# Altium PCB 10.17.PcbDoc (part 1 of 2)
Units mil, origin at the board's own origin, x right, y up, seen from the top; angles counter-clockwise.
Board outline 3750 x 1920 mil, 2 copper layers (Top Layer, Bottom Layer), stack 30.359 mil thick; 119 components, 118 nets, 550 pads, 365 vias.
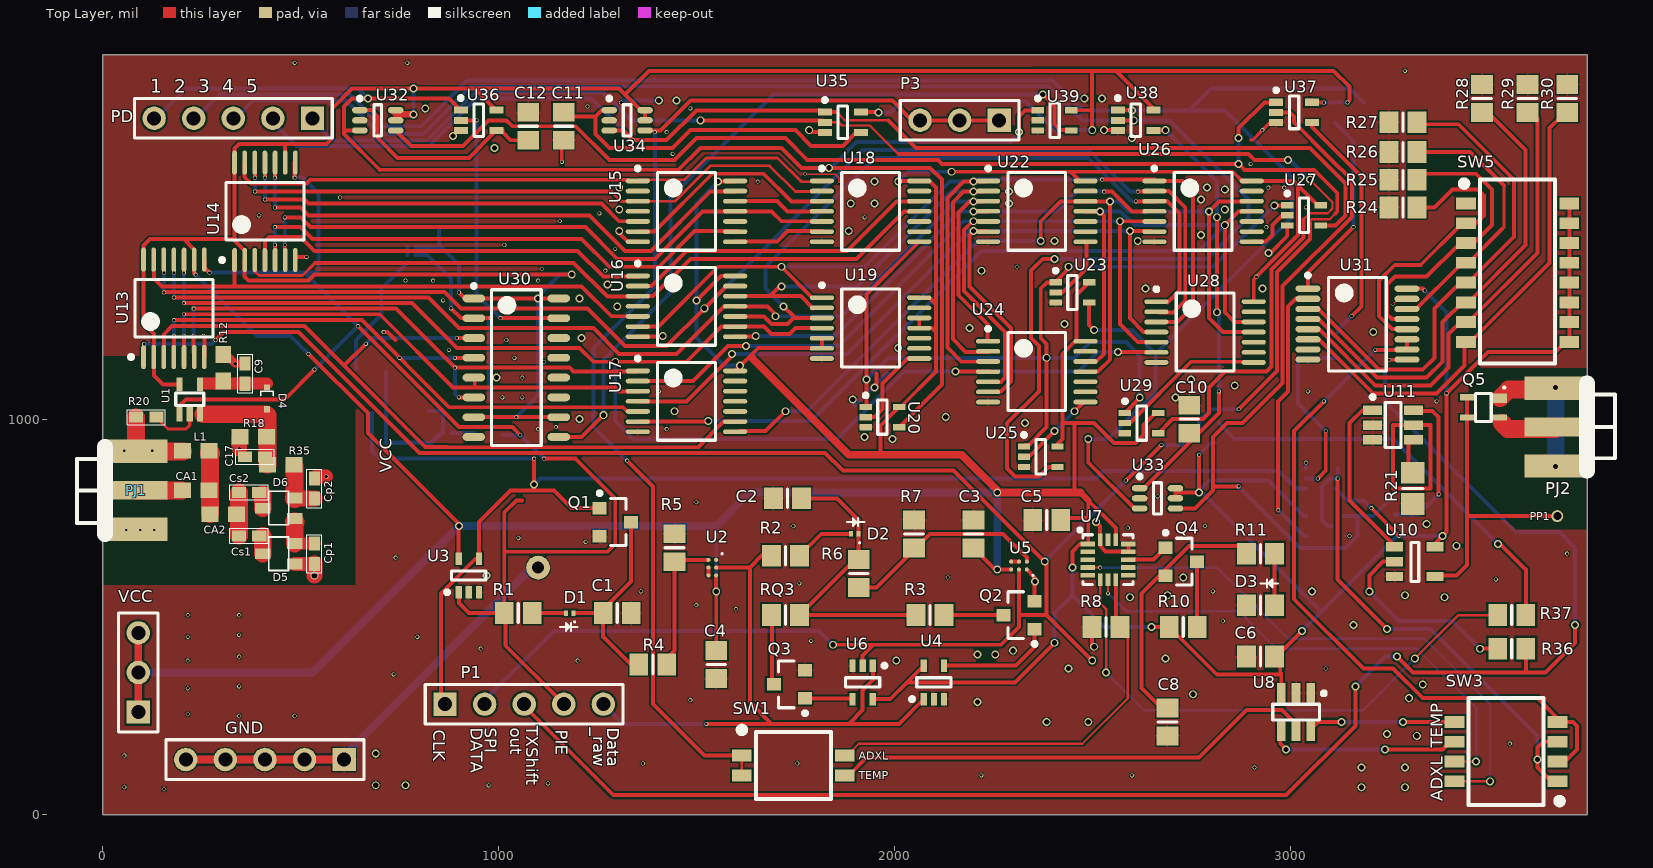
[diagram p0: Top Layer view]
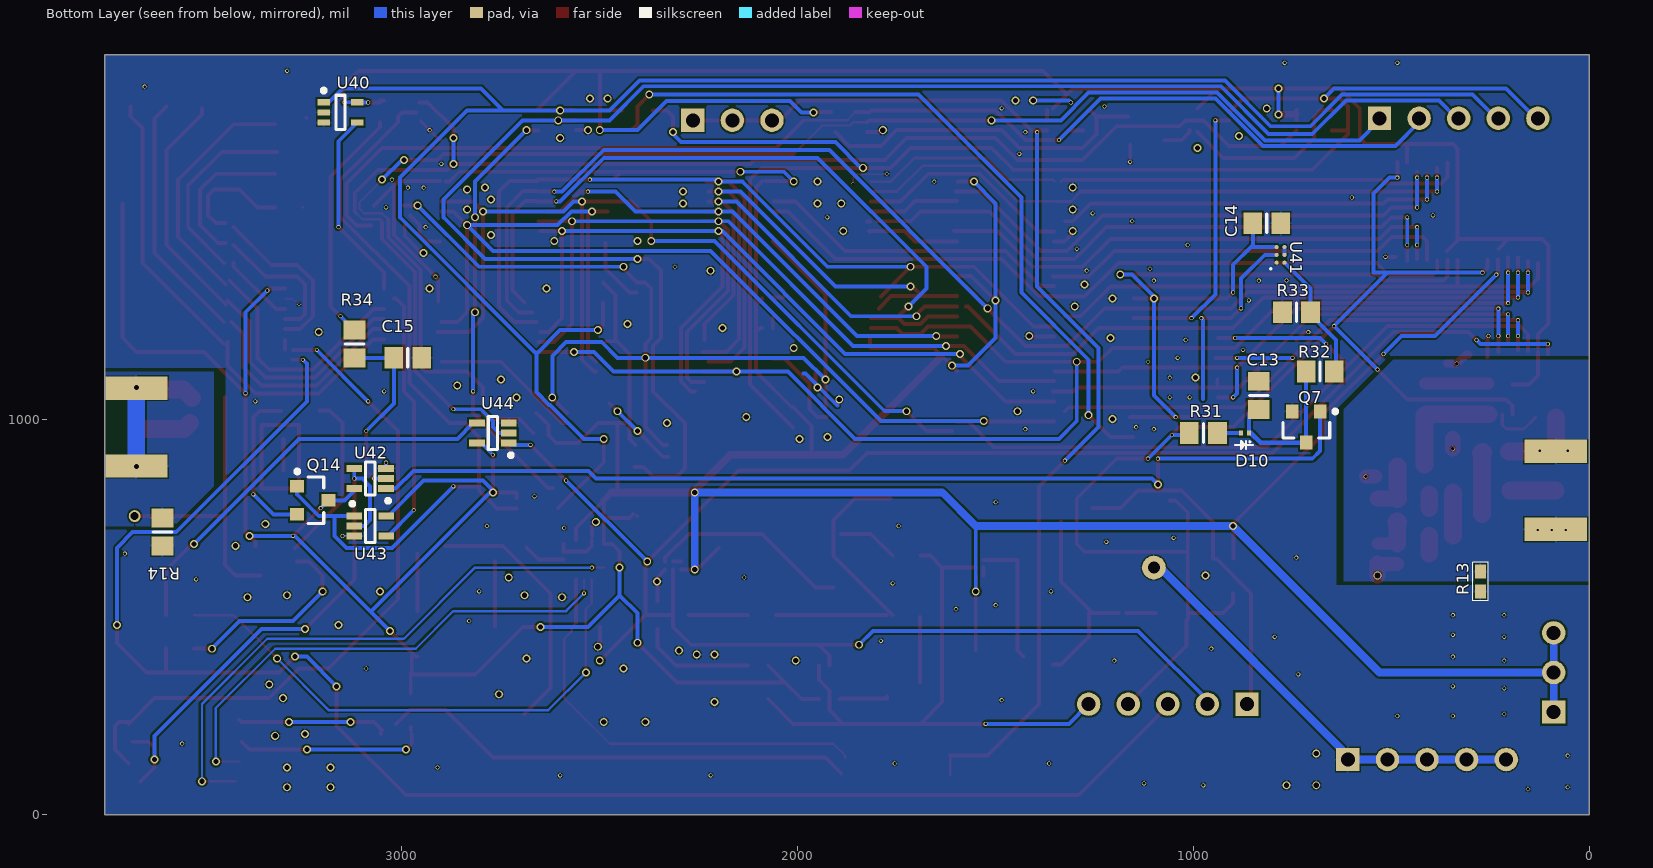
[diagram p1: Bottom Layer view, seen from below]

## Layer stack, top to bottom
Top Solder: solder mask 0.4, Solder Resist, Dk 3.5
Top Layer: signal copper 1.4
Dielectric 1: core 27.5591, FR-4, Dk 4.2
Bottom Layer: signal copper 1.4
Bottom Solder: solder mask 0.4, Solder Resist, Dk 3.5

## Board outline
0,0 3750,0 3750,1920 0,1920

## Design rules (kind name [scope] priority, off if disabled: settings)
Clearance Clearance_1 [InPolygon] p1: gap=5 ignorepadtopadclearanceinfootprint=FALSE except(0: Arc-Hole Track-Hole SMDPad-Hole THPad-Hole Via-Hole Fill-Hole Poly-Hole Region-Hole Text-Hole)
Clearance [All] p2: gap=4 ignorepadtopadclearanceinfootprint=FALSE except(0: Arc-Hole Track-Hole SMDPad-Hole THPad-Hole Via-Hole Fill-Hole Poly-Hole Region-Hole Text-Hole)
ComponentClearance [All] p1 off: gap=4 collisioncheckmode=3 verticalgap=10 showdistances=FALSE
PlaneClearance [All] p1: clearance=0
PolygonConnect [All] p1: connectstyle=Relief reliefconductorwidth=5 reliefentries=4 polygonreliefangle="90 Angle" airgapwidth=3
RoutingVias [All] p1: holewidth=8 width=150 viastyle="Through Hole" minholewidth=28 minwidth=50 maxholewidth=28 maxwidth=50
SolderMaskExpansion [All] p1: expansion=1
Width [All] p1: maxlimit=100 minlimit=4 preferedwidth=8 minimp=50.000000 maximp=50.000000 favimp=50.000000
28 further rules are at their usual default settings.

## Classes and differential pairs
component class Uplink: C5 C6 C8 D3 PJ2 PP1 Q4 Q5 Q14 R8 R10 R11 R14 R21 R24 R25 R26 R27 R28 R29 R30 R36 R37 SW3 SW5 U7 U8 U10 U11 U31
component class PIE_to_SPI: C1 C2 C3 C4 C13 C14 D1 D2 D10 GND P1 Q1 Q2 Q3 Q7 R1 R2 R3 R4 R5 R6 R7 R31 R32 R33 RQ3 U2 U3 U4 U5 U6 U41 VCC
component class AFE: C9 C17 CA1 CA2 Cp1 Cp2 Cs1 Cs2 D4 D5 D6 L1 PJ1 R12 R13 R18 R20 R35 U1
component class FSM: C10 C11 C12 C15 P3 PD R34 SW1 U13 U14 U15 U16 U17 U18 U19 U20 U22 U23 U24 U25 U26 U27 U28 U29 U30 U32 U33 U34 U35 U36 U37 U38 U39 U40 U42 U43 U44

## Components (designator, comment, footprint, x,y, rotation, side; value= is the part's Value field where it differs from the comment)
C1 "4.7nf" 6-0805_N 1300,510 r180 top value=100pF
C2 "4.7nf" 6-0805_N 1730,800 r0 top value=100pF
C3 "100nF" 6-0805_N 2200,710 r270 top value=100pF
C4 "100nF" 6-0805_N 1550,380 r90 top value=100pF
C5 "100nF" 6-0805_N 2385,745 r0 top value=100pF
C6 "100nF" 6-0805_N 2925,400 r0 top value=100pF
C8 "22uF" 6-0805_N 2690,235 r90 top value=100pF
C9 "Ceramic_Chip_Capacitor" 0402 360,1115 r90 top value=1uF
C10 "30pf" 6-0805_N 2745,1000 r270 top value=100pF
C11 "30pf" 6-0805_N 1165,1740 r90 top value=100pF
C12 "30pf" 6-0805_N 1075,1740 r270 top value=100pF
C13 "4.7nf" 6-0805_N 835,1060 r270 bottom value=100pF
C14 "100nF" 6-0805_N 815,1495 r0 bottom value=100pF
C15 "22pf" 6-0805_N 2985,1155 r0 bottom value=100pF
C17 "Ceramic_Chip_Capacitor" 0402 385,905 r180 top value=33pF
CA1 "Ceramic Chip Capacitor" 0603 235,820 r0 top value=tune
CA2 "Ceramic Chip Capacitor" 0603 305,760 r0 top value=tune
Cp1 "Ceramic_Chip_Capacitor" 0402 535,660 r270 top value=10pF
Cp2 "Ceramic_Chip_Capacitor" 0402 535,825 r90 top value=10pF
Cs1 "Ceramic_Chip_Capacitor" 0402 370,705 r0 top value=7pF
Cs2 "Ceramic_Chip_Capacitor" 0402 370,815 r0 top value=7pF
D1 "PMEG1201AESF" DIODE 1180,510 r180 top
D2 "PMEG1201AESF" DIODE 1900,710 r180 top
D3 "LED" 6-0805_N 2925,530 r180 top
D4 "RB751S40T1" SOD-523 415,1080 r0 top
D5 "HSMS-285C" "SOT-323, HSMS-285C" 445,660 r90 top
D6 "HSMS-285C" "SOT-323, HSMS-285C" 445,775 r90 top
D10 "PMEG1201AESF" DIODE 870,965 r0 bottom
GND "Header 5" HDR1X5 610,140 r180 top (schematic designator Pgnd)
L1 "Inductor" 0603 235,920 r0 top value=tune
P1 "Header 5" HDR1X5 865,280 r0 top
P3 "Header 3" HDR1X3 2265,1755 r180 top
PD "Header 5" HDR1X5 530,1760 r180 top (schematic designator P_PD)
PJ1 "SMA" SMA 85.91,819.92 r0 top
PJ2 "SMA" SMA 3670,980 r180 top
PP1 "Probe Point" "Probe Point" 3320,705 r90 top
Q1 "DMG2302UK" NMOS-DMG2302UK 1295,740 r0 top
Q2 "DMG2302UK" NMOS-DMG2302UK 2315,505 r180 top
Q3 "DMG2302UK" NMOS-DMG2302UK 1735,330 r180 top
Q4 "DMG2302UK" NMOS-DMG2302UK 2725,640 r0 top
Q5 "BF1212WR" sot343r 3490,1030 r90 top
Q7 "DMG2302UK" NMOS-DMG2302UK 715,980 r270 bottom
Q14 "DMG2302UK" NMOS-DMG2302UK 3225,795 r180 bottom
R1 "7.5K" 6-0805_N 1050,510 r0 top value=1K
R2 "1.62k" 6-0805_N 1725,655 r0 top value=1K
R3 "9.76K" 6-0805_N 2090,505 r0 top value=1K
R4 "180K" 6-0805_N 1390,380 r0 top value=1K
R5 "410k" 6-0805_N 1445,675 r90 top value=1K
R6 "180K" 6-0805_N 1910,610 r270 top value=1K
R7 "410k" 6-0805_N 2050,710 r90 top value=1K
R8 "1M" 6-0805_N 2535,475 r0 top value=1K
R10 "0R" 6-0805_N 2730,475 r0 top value=1K
R11 "470R" 6-0805_N 2925,660 r180 top value=1K
R12 "Resistor" 0603 305,1130 r270 top value=360k
R13 "Resistor" 0402 275,590 r90 bottom value=0R
R14 "0R" 6-0805_N 3605,715 r270 bottom value=1K
R18 "Resistor" 0603 380,955 r180 top value=412k
R20 "Resistor" 0402 110,1005 r180 top value=0R
R21 "Resistor" 6-0805_M 3310,825 r90 top
R24 "8.4M" 6-0805_N 3285,1535 r180 top value=1K
R25 "8.4M" 6-0805_N 3285,1605 r180 top value=1K
R26 "8.4M" 6-0805_N 3285,1675 r180 top value=1K
R27 "8.4M" 6-0805_N 3285,1750 r0 top value=1K
R28 "8.4M" 6-0805_N 3485,1810 r270 top value=1K
R29 "8.4M" 6-0805_N 3600,1810 r270 top value=1K
R30 "8.4M" 6-0805_N 3700,1810 r270 top value=1K
R31 "100R" 6-0805_N 975,965 r180 bottom value=1K
R32 "180K" 6-0805_N 680,1120 r180 bottom value=1K
R33 "410k" 6-0805_N 740,1270 r0 bottom value=1K
R34 "7.5K" 6-0805_N 3120,1190 r270 bottom value=1K
R35 "Resistor" 0603 450,885 r180 top value=0R
R36 "0R" 6-0805_N 3560,420 r0 top value=1K
R37 "0R" 6-0805_N 3560,505 r180 top value=1K
RQ3 "0R" 6-0805_N 1725,505 r0 top value=1K
SW1 "DIP 1.27*2" KEY1.27*2new 1875,150 r270 top
SW3 "DIP 1.27*4" KEY1.27*4 3675.63,85 r90 top
SW5 "DIP 1.27*8" KEY1.27*8 3444.37,1545 r270 top
U1 "NCS2200SQ2T2G" sc70-5 220,1050 r0 top
U2 "MAX9039B" BGA6-UCSP6 1540.16,625 r270 top
U3 "NL17SZ02DFT2G" "SC-88A (SC-70-5/SOT-353)" 925,605 r90 top
U4 "NL17SZ02DFT2G" "SC-88A (SC-70-5/SOT-353)" 2100,335 r90 top
U5 "MAX9039B" BGA6-UCSP6 2315,630 r180 top
U6 "NL17SZ02DFT2G" "SC-88A (SC-70-5/SOT-353)" 1920,335 r270 top
U7 "ADXL362" ADXL362 2540,645 r0 top
U8 "max6629" MAX6629-6632 3015,260 r270 top
U10 "SN74LV1T86DBVR" "SOT-23-5 -D" 3315,640 r270 top
U11 "LTC6906" LTC6906 3260,985 r0 top
U13 "SN74HC164PW" Tssop14(shift8) 180,1280 r90 top
U14 "SN74HC164PW" Tssop14(shift8) 410,1525 r90 top
U15 "SN74LVC14APW" Tssop14(shift8) 1475,1525 r0 top
U16 "SN74LVC14APW" Tssop14(shift8) 1475,1285 r0 top
U17 "SN74LVC14APW" Tssop14(shift8) 1475,1045 r0 top
U18 "CD74HC30PW" Tssop14(shift8) 1940,1525 r0 top
U19 "CD74HC30PW" Tssop14(shift8) 1940,1230 r0 top
U20 "NL17SZ02DFT2G" "SC-88A (SC-70-5/SOT-353)" 1970,1005 r0 top
U22 "CD74HC30PW" Tssop14(shift8) 2360,1525 r0 top
U23 "NL17SZ02DFT2G" "SC-88A (SC-70-5/SOT-353)" 2450,1320 r0 top
U24 "CD74HC30PW" Tssop14(shift8) 2360,1120 r0 top
U25 "NL17SZ02DFT2G" "SC-88A (SC-70-5/SOT-353)" 2370,905 r0 top
U26 "CD74HC30PW" Tssop14(shift8) 2780,1525 r0 top
U27 "NL17SZ02DFT2G" "SC-88A (SC-70-5/SOT-353)" 3035,1515 r0 top
U28 "CD74HC30PW" Tssop14(shift8) 2785,1220 r0 top
U29 "NL17SZ02DFT2G" "SC-88A (SC-70-5/SOT-353)" 2625,990 r0 top
U30 "SN74LV163ADR(Counter)" SOIC127P600X265-16N 1045,1130 r0 top
U31 "SN74HC165PW" TSSOP16(COUNTER) 3170,1240 r0 top
U32 "NC7SZ175P6X" SC-70 695,1755 r0 top
U33 "NC7SZ175P6X" SC-70 2665,800 r0 top
U34 "NC7SZ175P6X" SC-70 1325,1755 r0 top
U35 "SN74AUP1G32DCK(OR GATE)" SN74AUP1G32DCK（OR-gate-SC70-DCK） 1870,1750 r0 top
U36 "SN74AUP1G32DCK(OR GATE)" SN74AUP1G32DCK（OR-gate-SC70-DCK） 950,1755 r0 top
U37 "SN74AUP1G32DCK(OR GATE)" SN74AUP1G32DCK（OR-gate-SC70-DCK） 3010,1775 r0 top
U38 "SN74AUP1G32DCK(OR GATE)" SN74AUP1G32DCK（OR-gate-SC70-DCK） 2610,1755 r0 top
U39 "NL17SZ02DFT2G" "SC-88A (SC-70-5/SOT-353)" 2405,1755 r0 top
U40 "NL17SZ02DFT2G" "SC-88A (SC-70-5/SOT-353)" 3155,1775 r180 bottom
U41 "MAX9039B" BGA6-UCSP6 780,1415 r90 bottom
U42 "SN74AHC1G08DCK(And gate)" AND-gate-SC70-DCK 3080,850 r0 bottom
U43 "SN74AHC1G08DCK(And gate)" AND-gate-SC70-DCK 3080,730 r180 bottom
U44 "SN74AHC1G08DCK(And gate)" AND-gate-SC70-DCK 2770,965 r0 bottom
VCC "Header 3" HDR1X3 90,260 r90 top (schematic designator Pvcc)

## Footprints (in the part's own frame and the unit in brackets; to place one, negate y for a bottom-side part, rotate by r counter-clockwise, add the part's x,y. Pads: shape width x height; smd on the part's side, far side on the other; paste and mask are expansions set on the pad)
6-0805_M [mm] "Chip Resistor, Body 2.0x1.2mm, IPC Low Density"
  rect 1.4x1.5 smd: 1(-1,0) 2(1,0)
  silkscreen extent 0,-0.65 0,0.65, body extent -1.07,-0.7 1.07,0.7, height 0.7
6-0805_N [mm] "Chip Resistor, Body 2.0x1.2mm, IPC Medium Density"
  rect 1.2x1.4 smd: 1(-0.9,0) 2(0.9,0)
  silkscreen extent 0,-0.6 0,0.6, body extent -1.07,-0.7 1.07,0.7, height 0.7
0402 [mm] "Chip Capacitor; Body 1.0 x 0.5 mm (LxW typ)"
  rect 0.9x0.7 smd: 1(-0.65,0) 2(0.65,0)
  silkscreen extent -1.23,-0.48 1.23,0.48
0603 [mm] "Chip Capacitor; Body 1.6 x 0.8 mm (LxW typ)"
  rect 1.1x1 smd: 1(-0.85,0) 2(0.85,0)
ADXL362 [mm]
  rect 0.925x0.3 smd mask+0.051: 1(-1.3,1) 2(-1.3,0.5) 3(-1.3,0) 4(-1.3,-0.5) 5(-1.3,-1) 9(1.3,-1) 10(1.3,-0.5) 11(1.3,0) 12(1.3,0.5) 13(1.3,1)
  rect 0.3x0.8 smd mask+0.051: 6(-0.5,-1.275) 7(0,-1.275) 8(0.5,-1.275) 14(0.5,1.275) 15(0,1.275) 16(-0.5,1.275)
  silkscreen extent -1.9,-1.6 1.6,2, body extent -1.5,-1.5 1.5,1.5, height 1.14
AND-gate-SC70-DCK [mm] "SOT23, 5-Leads, Body 2.10x2.35mm, Pitch 0.65mm, IPC Medium Density"
  rect 1x0.45 smd: 1(-1.016,0.65) 2(-1.016,0) 3(-1.016,-0.65) 4(1.023,-0.65) 5(1.023,0.65)
  silkscreen extent -1.27,-1.05 0.3,1.55, body extent -0.7,-1.05 0.7,1.05, height 1.1
BGA6-UCSP6 [mm] "BGA, 6-Leads, Body 1.57x1.05mmx0.69mm, Pitch 1.00mm"
  round 0.26 smd: A1(-0.5,0.25) A2(0,0.25) A3(0.5,0.25) B1(-0.5,-0.25) B2(0,-0.25) B3(0.5,-0.25)
  silkscreen extent -0.94,0.58 -0.84,0.68, body extent -0.78,-0.53 0.79,0.53, height 0.69
DIODE [mm] "DFN, 2-Leads, Body 0.30x0.60mm, Pitch 0.40mm, IPC Medium Density"
  rect 0.25x0.35 smd: 1(-0.25,0) 2(0.25,0)
  silkscreen extent -0.37,0.52 -0.27,0.61, body extent -0.32,-0.17 0.31,0.16, height 0.32
HDR1X3 [mm] "Connector; Header; 3 Position"
  rect 1.5x1.5 hole 0.9: 1(0,0)
  round 1.5 hole 0.9: 2(2.54,0) 3(5.08,0)
  silkscreen extent -1.27,-1.27 6.35,1.27
HDR1X5 [mm] "Connector; Header; 5 Position"
  rect 1.5x1.5 hole 0.9: 1(0,0)
  round 1.5 hole 0.9: 2(2.54,0) 3(5.08,0) 4(7.62,0) 5(10.16,0)
  silkscreen extent -1.27,-1.27 11.43,1.27
KEY1.27*2new [mm]
  rect 0.76x1.27 smd: 1(0,-6.62) 2(1.27,-6.62) 3(0,0) 4(1.27,0)
  silkscreen extent -1.83,-6.78 2.79,-0.89
KEY1.27*4 [mm]
  rect 0.76x1.27 smd: 1(0,0) 2(1.27,0) 3(2.54,0) 4(3.81,0) 5(3.81,6.62) 6(2.54,6.62) 7(1.27,6.62) 8(0,6.62)
  silkscreen extent -1.52,-0.31 5.33,5.71
KEY1.27*8 [mm]
  rect 0.76x1.27 smd: 1(0,0) 2(1.27,0) 3(2.54,0) 4(3.81,0) 5(5.08,0) 6(6.35,0) 7(7.62,0) 8(8.89,0) 9(8.89,6.62) 10(7.62,6.62) 11(6.35,6.62) 12(5.08,6.62) 13(3.81,6.62) 14(2.54,6.62) 15(1.27,6.62) 16(0,6.62)
  silkscreen extent -1.52,-0.31 10.29,5.72
LTC6906 [mm] "SOT23, 6-Leads, Body 2.90x2.80mm, Pitch 0.95mm, IPC Medium Density"
  rect 1.22x0.6 smd: 1(-1.31,0.95) 2(-1.31,0) 3(-1.31,-0.95) 4(1.31,-0.95) 5(1.31,0) 6(1.31,0.95)
  silkscreen extent -1.43,-1.45 0.5,1.92, body extent -0.87,-1.45 0.87,1.45, height 1
MAX6629-6632 [mm] "SOT23, 6-Leads, Body 2.90x2.80mm, Pitch 0.95mm, IPC Medium Density"
  rect 1.33x0.56 smd: 1(-1.2,0.95) 2(-1.2,0) 3(-1.2,-0.95) 4(1.2,-0.95) 5(1.2,0) 6(1.2,0.95)
  silkscreen extent -1.32,-1.5 0.5,1.91, body extent -0.87,-1.5 0.87,1.5, height 1.45
NMOS-DMG2302UK [mm]
  rect 0.9x0.8 smd: 1(-1,0.9) 2(-1,-0.9) 3(1,0)
  silkscreen extent -1.12,-1.5 0.7,1.97, body extent -0.7,-1.5 0.7,1.5, height 1.1
"Probe Point" [mil] "35mil Pad, 20mil hole size"
  round 30 hole 20: 0(50,-355)
sc70-5 [mm] "SC70-5"
  rect 0.4x0.92 smd: 1(-0.65,-0.95) 2(0,-0.95) 3(0.65,-0.95) 4(0.65,0.95) 5(-0.65,0.95)
  silkscreen extent -0.9,-0.4 0.9,0.4
SC-70 [mm] "SOP, 6-Leads, Body 2.00x1.25mm, Pitch 0.65mm, IPC Medium Density"
  oval 1x0.4 smd: 1(-1.15,0.65) 2(-1.15,0) 3(-1.15,-0.65) 4(1.15,-0.65) 5(1.15,0) 6(1.15,0.65)
  silkscreen extent -1.27,-1 0.25,1.52, body extent -0.65,-1 0.65,1, height 2.65
"SC-88A (SC-70-5/SOT-353)" [mm] "SOT23, 5-Leads, Body 2.00x2.10mm, Pitch 0.65mm, IPC Medium Density"
  rect 0.8x0.4 smd: 1(-1.075,0.65) 2(-1.075,0) 3(-1.075,-0.65) 4(1.075,-0.65) 5(1.075,0.65)
  silkscreen extent -1.2,-1.1 0.3,1.52, body extent -0.67,-1.1 0.67,1.1, height 1.1
SMA [mm]
  rect 4x1.2 smd: 1(-0.023,0.002)
  rect 4x1.5 smd: 2(-0.023,-2.498) 2(-0.023,2.502)
  rect 4x1.5 smd far side: 2(-0.023,-2.498) 2(-0.023,2.502)
  silkscreen extent -3.83,-2.8 -1.93,2.8
SN74AUP1G32DCK（OR-gate-SC70-DCK） [mm] "SOT23, 5-Leads, Body 2.10x2.35mm, Pitch 0.65mm, IPC Medium Density"
  rect 0.9x0.45 smd: 1(-1.15,0.65) 2(-1.15,0) 3(-1.15,-0.65) 4(1.15,-0.65) 5(1.15,0.65)
  silkscreen extent -1.27,-1.05 0.3,1.55, body extent -0.7,-1.05 0.7,1.05, height 1.1
SOD-523 [mm] "SOD-523 Footprint"
  rect 0.4x0.4 smd: 1(0,0) 2(0,-1.4)
  silkscreen extent -0.4,-0.53 0.4,-0.25
SOIC127P600X265-16N [mm] "SOIC, 16-Leads, Body 10.00x4.00mm, Pitch 1.27mm, IPC Medium Density"
  oval 1.45x0.5 smd: 1(-2.725,4.445) 2(-2.725,3.175) 3(-2.725,1.905) 4(-2.725,0.635) 5(-2.725,-0.635) 6(-2.725,-1.905) 7(-2.725,-3.175) 8(-2.725,-4.445) 9(2.725,-4.445) 10(2.725,-3.175) 11(2.725,-1.905) 12(2.725,-0.635) 13(2.725,0.635) 14(2.725,1.905) 15(2.725,3.175) 16(2.725,4.445)
  silkscreen extent -2.85,-5 1.6,5.37, body extent -2,-5 2,5, height 2.65
sot343r [mm] "SOT343R Package for BF1212"
  rect 0.6x0.92 smd: 1(0.584,-1.016)
  rect 0.4x0.92 smd: 2(-0.664,-1.007) 3(-0.664,1.093) 3(0.636,1.093)
  silkscreen extent -0.91,-1.3 1.27,0.54
"SOT-23-5 -D" [mm] "SOT-23/SC-74A; 5 Leads; Body 3 x 3.1 mm, inc. leads (LxW max)"
  rect 0.6x1.1 smd: 1(-0.95,-1.3) 2(0,-1.3) 3(0.95,-1.3) 4(0.95,1.3) 5(-0.95,1.3)
  silkscreen extent -1.22,-0.25 1.27,0.25
"SOT-323, HSMS-285C" [mm] "SOT-323/SC-70; 3 Leads; HSMS-285C"
  rect 0.7x1 smd: 1(-0.65,-1.025) 2(0.65,-1.025) 3(0,1.025)
  silkscreen extent -1.07,-0.65 1.07,0.65
Tssop14(shift8) [mm] "SOP, 14-Leads, Body 5.00x4.50mm, Pitch 0.65mm, IPC Medium Density"
  oval 1.55x0.3 smd: 1(-3.125,1.95) 2(-3.125,1.3) 3(-3.125,0.65) 4(-3.125,0) 5(-3.125,-0.65) 6(-3.125,-1.3) 7(-3.125,-1.95) 8(3.125,-1.95) 9(3.125,-1.3) 10(3.125,-0.65) 11(3.125,0) 12(3.125,0.65) 13(3.125,1.3) 14(3.125,1.95)
  silkscreen extent -3.25,-2.5 1.85,2.87, body extent -2.25,-2.5 2.25,2.5, height 2.65
TSSOP16(COUNTER) [mm] "SOP, 16-Leads, Body 6.00x4.50mm, Pitch 0.65mm, IPC Medium Density"
  oval 1.6x0.4 smd: 1(-3.175,2.275) 2(-3.175,1.625) 3(-3.175,0.975) 4(-3.175,0.325) 5(-3.175,-0.325) 6(-3.175,-0.975) 7(-3.175,-1.625) 8(-3.175,-2.275) 9(3.175,-2.275) 10(3.175,-1.625) 11(3.175,-0.975) 12(3.175,-0.325) 13(3.175,0.325) 14(3.175,0.975) 15(3.175,1.625) 16(3.175,2.275)
  silkscreen extent -3.3,-3 1.85,3.25, body extent -2.25,-3 2.25,3, height 2.65

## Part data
C1 C2 C3 C4 C5 C6 C8 C10 C11 C12 C13 C14 C15: library part Cap, "Capacitor"
C9 C17 CA1 CA2 Cp1 Cp2 Cs1 Cs2: "Ceramic Capacitor - Standard"
D1 D2 D10: library part DIODE, "Schottky Diode"
D3: library part LED0, "Typical INFRARED GaAs LED"
D4: library part "Schottky Diode", "Schottky Diode"
D5 D6: "Agilent Schottky Diode, Bridge Quad, HSMS-285C"
GND P1 PD: "Header, 5-Pin"
P3 VCC: "Header, 3-Pin"
PP1: "Probe Point for debug"
Q1 Q2 Q3 Q4 Q7 Q14: library part MOSFET-N, "N-Channel MOSFET", PackageDocument=1995/1996
Q5: library part BF1212
R1 R2 R3 R4 R5 R6 R7 R8 R10 R11 R14 R24 R25 R26 R27 R28 R29 R30 R31 R32 R33 R34 R36 R37 RQ3: library part Res2, "Resistor"
R12 R13 R18 R20 R21 R35: "Thick Film Resistor"
SW1: library part KEY1.27*2
SW3: library part KEY1.27*4
SW5: library part KEY1.27*8
U1: "On Semi 10uA Comparator"
U2 U5 U41: library part Comparator
U3 U4 U6 U20 U23 U25 U27 U29 U39 U40: library part "NOR GATE"
U7: "Analog Devices low power accelerometer"
U10: library part "XOR GATE"
U13 U14: library part SN74HC164
U30: library part SN74LV163APW(Counter)

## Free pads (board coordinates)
  round 60 hole 30: 0(1100,625)

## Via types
v1: diameter 20, hole 13, Top Layer to Bottom Layer, 179 vias
v2: diameter 10, hole 6.5, Top Layer to Bottom Layer, 137 vias
v3: diameter 10, hole 7, Top Layer to Bottom Layer, 28 vias
v4: diameter 10, hole 8, Top Layer to Bottom Layer, 10 vias
v5: diameter 10, hole 6, Top Layer to Bottom Layer, 7 vias
v6: diameter 8, hole 6, Top Layer to Bottom Layer, 2 vias
v7: diameter 20, hole 15, Top Layer to Bottom Layer, 1 vias
v8: diameter 10, hole 6.5, Top Layer to Bottom Layer, tented top, 1 vias

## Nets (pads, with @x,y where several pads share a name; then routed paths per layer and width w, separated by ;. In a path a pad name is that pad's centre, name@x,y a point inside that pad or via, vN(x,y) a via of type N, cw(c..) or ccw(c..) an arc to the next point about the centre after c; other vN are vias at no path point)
ACCINT: Q4.1 U7.11 | length 106.9
  Top Layer w10: U7.11@2591.18,645 2655,645 ; 2655.2,645 Q4.1@2685.63,675.43
ADXL_CS: R8.2 SW1.3 U7.8 | length 1087.4
  Top Layer w6: SW1.3@1880,145 1880,150 1910,180 2475,180 2590,295 2590,445 2570.43,464.57 R8.2@2570.43,475 R8.2@2559.69,485.75
  Top Layer w10: R8.2@2559.69,485.75 U7.8@2559.69,594.8
ANT: CA1.1 PJ1.1 | length 115
  Top Layer w45: PJ1.1@85,820 CA1.1@200,820
B: R24.1 SW5.2 U31.12 | length 727.2
  Top Layer w10: U31.12@3295,1227.2 3257.8,1227.2 3225,1260 3225,1350 3265,1390 3330,1390 SW5.2@3425,1485 ; R24.1@3320.43,1535 3365,1535 3410,1580 3475,1580 3490,1565 3490,1515 3470,1495 SW5.2@3445,1495
"Bit avrg": C9.1 D4.1 R12.2 U1.4 | length 167.4
  Top Layer w8: U1.4@245,1090 U1.4@245.12,1090.12 ; C9.1@360,1085 C9.1@365.12,1090.12
  Top Layer w30: 255,1090.12 365.12,1090.12 415,1090.12
BITLINE: C17.1 D4.2 R18.1 R35.2 U1.3 | length 288.2
  Top Layer w12: 412.4,1012.6 415,1010 ; 415,930 416.54,928.46
  Top Layer w45: 255,1012.6 412.4,1012.6 ; R35.2@416.54,885 416.54,928.46 416.54,1010
C: R25.1 SW5.3 U31.13 | length 731.7
  Top Layer w10: U31.13@3295,1252.8 3257.2,1252.8 3245,1265 3245,1340 3265,1360 3345,1360 SW5.3@3425,1440 ; R25.1@3320,1620 3470,1620 3510,1580 3510,1490 3465,1445 SW5.3@3445,1445
CLK: P1.1 Q1.1 Q7.1 U3.4 U42.1 | length 3433.9
  Top Layer w10: P1.1@860,285 855,290 855,560 942.32,647.32 U3.4@950.59,647.32 950.59,740.59 1030,820 1090,820 ; v2(1090,900) v1(1090,835) 1090,820 ; Q1.1@1255,775 1185,775 1140,820 1090,820
  Bottom Layer w10: Q7.1@680,1015 680,920 700,900 v2(1090,900) ; v1(1090,835) 1105,850 2510,850 2529,869 2971,869 3015.59,824.41 U42.1@3040,824.41
CLK_ADXL: SW3.8 U7.4 | length 1442.5
  Top Layer w6: U7.4@2488.82,625.32 2520.32,625.32 v5(2520,625) ; SW3.8@3419.37,85 3500,85 v1@3505,80
  Bottom Layer w6: v5(2520,625) 2815,625 2995,445 3340,445 3505,280 v1(3505,85)
CLK_TEMP: SW3.6 U8.4 | length 479.1
  Top Layer w10: U8.4@2975,205 2975,180 v1(2990,165) ; U8.4@2977.6,212.76 U8.4@2977.6,222.4 ; v1(3240,165) 3385,165 SW3.6@3405,185
  Bottom Layer w10: v1(2990,165) v1(3240,165)
"CONTROL BIT": P3.1 P3.2 P3.3 SW1.1 SW1.2 U34.4 | length 2845.2
  Top Layer w6: SW1.1@1612.5,147.5 1614.37,145.63 SW1.2@1614.37,100
  Top Layer w10: v2(1325,895) 1390,830 1390,280 1520,150 SW1.1@1614.37,150 SW1.1@1615,150 ; U34.4@1370.28,1729.41 1409.41,1729.41 1485,1805 1995,1805 2045,1755 2140,1755 2240,1755 P3.1@2265,1755
  Bottom Layer w10: v2(1325,895) 1240,980 1240,1180 1395,1335 v2(1395,1725)
D: R26.1 SW5.4 U31.14 | length 679
  Top Layer w8: 3535,1480 3540,1485 3540,1590
  Top Layer w10: U31.14@3295,1278.39 3318.39,1278.39 3425,1385 SW5.4@3425,1395 ; R26.1@3315,1675 3455,1675 3540,1590 ; SW5.4@3447.69,1395 3450,1395 3535,1480
DATA-CONTROL: U32.4 U37.1 U44.2 | length 3579.2
  Top Layer w6: 3050,1495 3050,1500 3055,1505 3100,1505 3115,1520
  Top Layer w10: U32.4@740.28,1729.41 779.69,1690 910,1690 975,1755 1020,1755 1035,1740 1195,1740 1280,1655 1445,1655 1460,1670 1500,1710 1725,1710 1780,1655 2110,1655 2120,1645 v1(2870,1645) 2885,1630 3060,1630 3119,1571 3119,1524 3115,1520 ; v1(2870,1710) 2870,1735 2935,1800 U37.1@2955,1800 ; v2@2870.43,1025.43 2967,1122 2967,1372 3050,1455 3050,1495
  Bottom Layer w10: U44.2@2740,965 2755,965 2770,980 2770,995 2800,1025 v2(2870,1025) ; v1(2870,1645) v1@2870,1705
DATA_RAW: P1.5 R2.1 U2.A2 U4.1 U6.1 | length 1615.3
  Top Layer w10: P1.5@1255,280 1260,285 P1.5@1255,285 ; v2(1525,230) 1690,230 ; U2.A2@1550,625 1635,625 ; R2.1@1689.57,655 1665,655 1635,625 ; U6.1@1945.59,377.32 1945.59,340.59 1920,315 1920,265 1885,230 ; U4.1@2074.41,292.68 2011.73,230 1885,230 ; 1635,625 1635,285 1690,230 ; 1690,230 1885,230
  Bottom Layer w10: P1.5@1260,280 P1.5@1265,280 1315,230 v2(1525,230)
DATAIN_ADXL: R37.2 U7.6 | length 1369.6
  Top Layer w6: U7.6@2520.31,594.8 2520.31,534.69 2535,520 v1(2535,360) ; v1(3315,395) 3425,505 R37.2@3525,505
  Bottom Layer w6: v1(2535,360) 2630,265 3185,265 v1(3315,395)
DL1-EN: C12.2 U32.1 U36.4 | length 528.3
  Top Layer w8: C12.2@1075,1704.57 C12.2@1075.43,1704.57
  Top Layer w10: U32.1@649.72,1780.59 679.41,1780.59 695,1765 695,1710 745,1660 925,1660 U36.4@990,1725 ; U36.4@1010,1730 1010,1725 1030.43,1704.57 C12.2@1075,1704.57
DL2-EN: C10.2 U33.1 U38.4 | length 1078.8
  Top Layer w10: U33.1@2619.72,825.59 2630.59,825.59 2820,1015 v2(2820,1070) ; U38.4@2655.28,1729.41 v1@2684.41,1729.41 ; v1(2815,1270) v1(2815,1510)
  Bottom Layer w10: v1(2685,1730) 2815,1600 v1(2815,1510) ; v1(2815,1270) 2820,1265 v2(2820,1070)
DL3-EN: C11.2 U34.1 U35.4 | length 875.4
  Top Layer w10: C11.2@1165,1765 1245,1765 ; U34.1@1265,1780 1260,1780 1245,1765 ; U35.4@1905,1725 1870,1690 1790,1690 1750,1730 1485,1730 1440,1685 1280,1685 1245,1720 1245,1765
E: R27.2 SW5.5 U31.3 | length 1237.7
  Top Layer w10: U31.3@3045,1278.39 3071.61,1278.39 3225,1125 3335,1125 3365,1155 3365,1280 SW5.5@3435,1350 ; R27.2@3320,1745 3425,1745 3565,1605 3565,1460 SW5.5@3445,1340
F: R28.2 SW5.6 U31.4 | length 1190
  Top Layer w10: U31.4@3045,1252.8 3072.2,1252.8 3220,1105 3345,1105 3385,1145 3385,1245 SW5.6@3440,1300 ; SW5.6@3445,1290 3595,1440 3595,1680 3505,1770 R28.2@3505,1785
G: R29.2 SW5.7 U31.5 | length 1189.9
  Top Layer w10: U31.5@3045,1227.2 3072.8,1227.2 3215,1085 3355,1085 3400,1130 3400,1215 SW5.7@3430,1245 ; SW5.7@3450,1245 3625,1420 3625,1760 R29.2@3595,1790
GND: C1.1 C2.1 C3.1 C4.1 C5.1 C6.1 C8.1 C10.1 C11.1 C12.1 C13.1 C14.1 C15.1 D3.2 GND.1 GND.2 GND.3 GND.4 GND.5 pad.0 Q1.2 Q2.2 Q3.2 Q7.2 R5.2 R7.2 R8.1 R13.1 R14.2 R21.1 R24.2 R25.2 R26.2 R27.1 R28.1 R29.1 R30.1 R33.2 U2.A1 U3.2 U3.3 U4.2 U4.3 U5.A1 U6.3 U7.12 U7.13 U7.16 U8.1 U8.2 U10.3 U11.2 U11.3 U13.7 U14.7 U15.7 U16.7 U17.7 U18.7 U19.7 U20.3 U22.7 U23.3 U24.7 U25.3 U26.7 U27.3 U28.7 U29.3 U30.8 U31.8 U31.15 U32.2 U33.2 U34.2 U35.3 U36.3 U37.3 U38.3 U39.2 U39.3 U40.2 U40.3 U41.A1 U42.3 U43.3 U44.3 | length 2723
  Top Layer w4: v2(1775,1620) 1776,1619 1851,1619 1860,1610 v6(1860,1595) ; v2(2900,1645) v2@2901,1644 ; v6(3260,1290) U31.15@3270,1300 ; U31.15@3273.98,1303.98 U31.15@3295,1303.98
  Top Layer w8: v2(1160,1650) C11.1@1160,1695 ; 2900.12,1705 2905,1705 v2(2930,1730) U37.3@2952.5,1752.5 ; R27.1@3240,1760 R27.1@3242.5,1762.5
  Top Layer w10: U13.7@256.77,1156.97 v3@256.77,1206.77 ; U14.7@490,1410 v3(515,1410) ; v2(710,1220) 720,1220 740,1200 ; v1@1300,1475 v1(1305,1475) ; 1310,1465 1326.77,1448.23 U15.7@1351.97,1448.23 ; U16.7@1351.97,1208.23 1413.23,1208.23 v1(1415,1210) ; v1@1790,1725 U35.3@1825,1725 ; v1(1950,1080) 1955,1085 1955,1115 ; U5.A1@2334.69,620.16 2354.37,600.47 Q2.2@2354.37,540.43 ; R8.1@2499.57,475 2499.57,430.43 v1(2505,425) ; v1(2510,740) 2520,730 U7.16@2520,705 ; U7.16@2520.31,695.2 2520.31,679.69 2534,666 2589.87,666 U7.12@2591.18,664.69 U7.13@2591.18,684.37 ; v1(2530,1730) U38.3@2560,1730 ; v1@2945,1425 v1(2945,1420) 2950,1420 2992.68,1462.68 U27.3@2992.68,1489.41
  Top Layer w20: GND.5@205,135 GND.5@210,140 GND.4@310,140 GND.3@410,140 GND.2@510,140 GND.1@610,140
  Bottom Layer w4: U43.3@3135,705 v4(3150,705)
  Bottom Layer w10: v4(1310,1800) 1315,1805 v1(1405,1805) ; 1900,1035 1980,1115 1985,1115 ; U42.3@3040,875 U42.3@3040,875.59 v2(3040,890)
  Bottom Layer w20: GND.5@210,140 GND.4@310,140 GND.3@410,140 GND.2@510,140 GND.1@600,140 ; GND.1@605,140 GND.1@600,140 ; pad.0@1090,630 GND.1@600,140
  other v1: 3180,70 3290,70 690,75 765,75 3180,120 3290,120 690,155 3320,200 3245,205 2385,235 2490,235 2210,285 3300,295 2755,305 3335,330 2440,370 2005,390 2685,395 2210,405 2255,405 2300,415 3160,480 2595,550 3390,550 2690,555 3290,555 3055,565 2355,590 2730,600 970,605 3420,680 3345,735 1995,950 1925,955 2330,990 1205,1000 2130,1005 1445,1020 1895,1050 2710,1055 2860,1085 2750,1100 995,1105 2010,1180 1210,1205 3210,1220 2190,1230 2430,1240 1300,1285 1205,1305 2635,1330 2930,1330 1275,1340 2220,1375 2405,1450 2615,1450 2775,1465 1885,1475 1305,1530 2835,1530 1890,1545 1950,1545 2290,1545 2775,1555 2290,1575 2835,1580 1305,1585 2790,1585 1950,1600 2600,1710 885,1715 1785,1730 815,1785 1450,1805 2480,1810 2525,1810
  other v2: 155,65 55,70 975,75 1125,80 2220,100 2600,100 2910,120 1365,130 1755,130 55,150 3555,180 345,250 485,250 215,255 1485,290 215,320 345,325 735,355 3090,370 215,390 1200,390 345,400 955,420 1790,440 215,450 795,450 345,455 2830,490 215,505 345,505 1600,520 1500,530 1360,565 2805,565 1760,585 3520,595 2135,600 740,650 3700,660 1220,690 1050,700 2590,725 1745,730 2785,730 1500,790 2665,805 1100,975 1425,975 1145,980 3370,1045 1010,1055 1060,1055 1405,1070 3045,1070 1060,1105 1115,1145 1040,1155 875,1175 1020,1200 860,1300 835,1350 1100,1350 1270,1375 1110,1380 2310,1385 1295,1430 1015,1440 2940,1485 1155,1500 1925,1510 395,1515 1255,1520 3040,1535 600,1560 2945,1585 2985,1585 1655,1600 3025,1605 1440,1670 1425,1725 1485,1785 3650,1840 3290,1880 485,1900 770,1900
  other v3: 255,1210 765,1350
  other v4: 1225,1790
H: R30.2 SW5.8 U31.6 | length 1237.8
  Top Layer w10: U31.6@3045,1201.61 3073.39,1201.61 3210,1065 3370,1065 3440,1135 SW5.8@3440,1195 ; SW5.8@3450,1190 3655,1395 3655,1735 3685.22,1765.22 R30.2@3685.22,1789.78
LOAD: U30.9 U39.4 | length 1932.2
  Top Layer w10: U30.9@1152.28,955 1210,955 v1(1265,1010) ; v1(2375,1820) 2405,1790 2405,1745 2420,1730 U39.4@2440,1730
  Bottom Layer w10: v1(1265,1010) 1265,1150 1435,1320 1435,1560 1695,1820 v1(2375,1820)
NetC1_2: C1.2 D1.1 Q1.3 R4.1 | length 509.4
  Top Layer w10: D1.1@1189.84,510 C1.2@1264.57,510 1264.57,450 ; C1.2@1259.78,514.78 1334.37,589.37 Q1.3@1334.37,740 ; 1265,450 1335,380 R4.1@1354.57,380
NetC2_2: C2.2 D2.1 R3.1 R6.1 RQ3.2 | length 748.5
  Top Layer w10: RQ3.2@1760.43,505 1909.84,654.41 D2.1@1909.84,710 1909.84,745.16 1855,800 C2.2@1765.43,800 ; RQ3.2@1775.28,505 R3.1@2054.57,505
NetC8_2: C8.2 Q4.2 R11.2 | length 646.2
  Top Layer w10: C8.2@2690,255.43 2625,320.43 2625,560 2745,680 R11.2@2890,680
NetC13_2: C13.2 D10.1 Q7.3 R32.1 | length 417
  Bottom Layer w10: Q7.3@715,940 715.43,940.43 715.43,940.63 R32.1@715.43,1120 ; C13.2@825,1020 855,1020 860.16,1014.84 D10.1@860.16,965
  Bottom Layer w12: Q7.3@715.43,940.63 830.63,940.63 855,965
NetC15_2: C15.2 R34.2 U42.2 | length 471.7
  Top Layer w10: v2(3070,850) 3090,870 v2(3090,970)
  Bottom Layer w10: C15.2@3020.43,1155 C15.2@3020.43,1154.57 ; U42.2@3040,850 v2(3070,850) ; v2(3090,970) 3020.43,1039.57 C15.2@3020.43,1154.57 ; R34.2@3120,1154.57 C15.2@3020.43,1154.57
NetCA1_2: CA1.2 CA2.1 L1.2 | length 155.6
  Top Layer w45: CA2.1@271.54,760 L1.2@271.54,913.46
  Top Layer w49: L1.2@270,915 L1.2@271.54,913.46
NetCA2_2: CA2.2 Cs1.1 Cs2.1 | length 109.4
  Top Layer w45: Cs1.1@344.41,705.59 Cs2.1@344.41,815
NetCp1_1: Cp1.1 D5.2 D6.1 | length 99.8
  Top Layer w10: D5.2@490,685 D5.2@490.59,685.59
  Top Layer w30: D5.2@490.59,685.59 Cp1.1@535,685.59
  Top Layer w45: D5.2@485.35,685.59 D6.1@485.35,739.65
  Top Layer w49: D6.1@485,740 D6.1@485.35,739.65
NetCp2_1: Cp2.1 D6.2 R35.1 | length 129.8
  Top Layer w40: D6.2@485,800 485.59,799.41 Cp2.1@535,799.41
  Top Layer w45: D6.2@485,800.94 R35.1@485,880
  Top Layer w49: D6.2@485,800.94 D6.2@485.35,800.59
NetCs1_2: Cs1.2 D5.3 | length 44.6
  Top Layer w45: D5.3@404.65,660 Cs1.2@404.65,704.65
NetCs2_2: Cs2.2 D6.3 | length 34.6
  Top Layer w45: D6.3@404.65,775 Cs2.2@404.65,809.65
NetD1_2: D1.2 R1.2 | length 74.7
  Top Layer w10: R1.2@1095.43,510 D1.2@1170.16,510
NetD2_2: D2.2 R2.2 | length 152.5
  Top Layer w10: R2.2@1760.43,655 1815.43,710 D2.2@1890.16,710
NetD3_1: D3.1 R11.1 | length 145
  Top Layer w10: D3.1@2960.43,515 R11.1@2960.43,660
NetD10_2: D10.2 R31.2 | length 59.6
  Bottom Layer w10: D10.2@880,965 R31.2@939.57,965
NetPJ2_1: PJ2.1 Q5.2 | length 141.2
  Top Layer w45: 3535,990 3550,975 PJ2.1@3670,975
NetQ2_3: Q2.3 R3.2 | length 150.2
  Top Layer w10: R3.2@2125.43,505 Q2.3@2275.63,505
NetQ3_1: Q3.1 U6.4 | length 130.6
  Top Layer w10: Q3.1@1774.37,294.57 Q3.1@1779.37,294.57 ; Q3.1@1774.37,299.57 Q3.1@1779.37,294.57 ; Q3.1@1781.26,292.68 Q3.1@1779.37,294.57 ; U6.4@1894.41,292.68 1892.52,294.57 Q3.1@1779.37,294.57
NetQ3_3: Q3.3 RQ3.1 | length 165
  Top Layer w10: Q3.3@1690.63,335 RQ3.1@1690.63,500
NetQ4_3: Q4.3 R10.2 | length 165.4
  Top Layer w6: R10.2@2764.37,476.06 R10.2@2765.43,475
  Top Layer w10: R10.2@2764.37,476.06 Q4.3@2764.37,640
NetQ14_2: Q14.2 U11.6 | length 402.7
  Top Layer w10: U11.6@3305,1020 3360,1020 3375,1005 v2(3375,810)
  Bottom Layer w10: Q14.2@3264.37,759.57 3324.57,759.57 v2(3375,810)
NetR4_2: R4.2 R5.1 U2.B1 | length 331.1
  Top Layer w10: R4.2@1430,400 1445,415 R5.1@1445,639.57 ; R5.1@1445,644.69 U2.B1@1530.32,644.69
NetR6_2: R6.2 R7.1 U5.B1 | length 516
  Top Layer w10: R6.2@1910,574.57 1955,574.57 2090.43,710 2275,710 2334.69,650.31 U5.B1@2334.69,639.84
NetR20_1: R20.1 U1.2 | length 129.2
  Top Layer w8: R20.1@135,1005 165,975 210,975 220,985 U1.2@220,1012.6
NetR21_2: R21.2 U11.4 | length 80.3
  Top Layer w10: R21.2@3299.37,870 3299.37,949.37 U11.4@3300,950
NetR32_2: R32.2 R33.1 U41.B1 | length 319
  Bottom Layer w10: R32.2@640,1125 640,1200 704.57,1264.57 R33.1@704.57,1270 ; R33.1@705,1275 705,1330.16 U41.B1@770.16,1395.31
NetU2_B2: U2.B2 U2.B3 | length 19.7
  Top Layer w10: U2.B3@1530.32,605.31 U2.B2@1530.32,625
NetU5_B2: U5.B2 U5.B3 | length 19.7
  Top Layer w10: U5.B3@2295.31,639.84 U5.B2@2315,639.84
